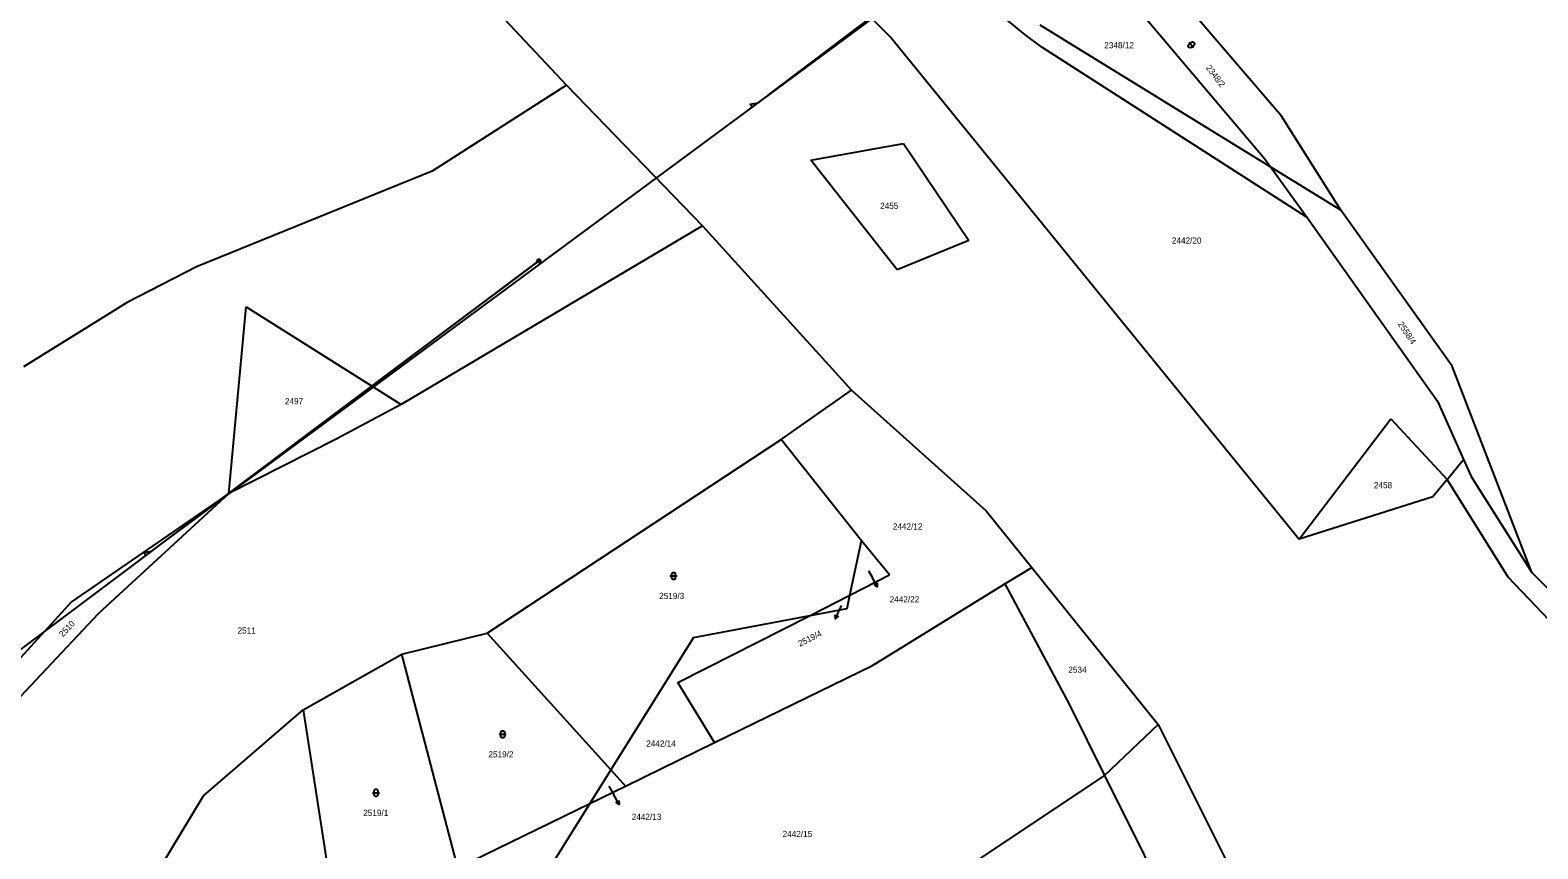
# Model space of a CAD drawing. Extents: x -747792 to -745414, y -1093712 to -1091463.
# Drawn here: x -747200 to -746990.9, y -1092715.2 to -1092601.7 of the extents above; entities that cross this region are included whole.
import ezdxf

# ---------------------------------------------------------------- set-up
doc = ezdxf.new("R2010")
doc.units = 0
for name, color, linetype in [('Pracovní_bod JDTM STC_VC', 7, 'Continuous'), ('Pracovní_bod JDTM STC_VC - číslo', 7, 'Continuous'), ('Pracovní_bod NN - výška', 7, 'Continuous'), ('Pracovní_bod polohopisu - výška', 7, 'Continuous'), ('Pracovní_bod polohopisu - číslo', 7, 'Continuous')]:
    doc.layers.add(name, color=color, linetype=linetype)

msp = doc.modelspace()

# ---------------------------------------------------------------- linework, layer by layer
at = {"layer": 'Pracovní_bod JDTM STC_VC - číslo'}
for points in [[(-747038.97, -1092603.39), (-747038.82, -1092603.33), (-747038.67, -1092603.37), (-747038.57, -1092603.49), (-747038.56, -1092603.64), (-747038.64, -1092603.77), (-747039.02, -1092604.09), (-747039.17, -1092604.15), (-747039.32, -1092604.11), (-747039.42, -1092603.99), (-747039.43, -1092603.84), (-747039.35, -1092603.71)], [(-747111.06, -1092677.12), (-747111.01, -1092676.98), (-747110.89, -1092676.89), (-747110.73, -1092676.89), (-747110.6, -1092676.98), (-747110.56, -1092677.12), (-747110.56, -1092677.62), (-747110.6, -1092677.77), (-747110.73, -1092677.85), (-747110.89, -1092677.85), (-747111.01, -1092677.77), (-747111.06, -1092677.62)], [(-747134.75, -1092699.08), (-747134.7, -1092698.94), (-747134.58, -1092698.85), (-747134.42, -1092698.85), (-747134.29, -1092698.94), (-747134.24, -1092699.08), (-747134.24, -1092699.58), (-747134.29, -1092699.73), (-747134.42, -1092699.81), (-747134.58, -1092699.81), (-747134.7, -1092699.73), (-747134.75, -1092699.58)], [(-747152.32, -1092707.2), (-747152.27, -1092707.05), (-747152.15, -1092706.96), (-747151.99, -1092706.96), (-747151.86, -1092707.05), (-747151.82, -1092707.2), (-747151.82, -1092707.7), (-747151.86, -1092707.84), (-747151.99, -1092707.94), (-747152.15, -1092707.94), (-747152.27, -1092707.84), (-747152.32, -1092707.7)]]:
    msp.add_lwpolyline(points, close=True, dxfattribs=at)
for points in [[(-747039.32, -1092603.36), (-747038.91, -1092603.84), (-747038.68, -1092604.12)], [(-747111.31, -1092677.37), (-747110.68, -1092677.37), (-747110.31, -1092677.37)], [(-747135, -1092699.33), (-747134.36, -1092699.33), (-747134, -1092699.33)], [(-747152.57, -1092707.45), (-747151.93, -1092707.45), (-747151.57, -1092707.45)]]:
    msp.add_lwpolyline(points, dxfattribs=at)
at = {"layer": 'Pracovní_bod NN - výška'}
for points in [[(-747062.09, -1092602.28), (-747127.32, -1092548.77)], [(-747108.12, -1092575.08), (-747080.59, -1092602.79)], [(-747152.98, -1092580.18), (-747125.63, -1092609.32)], [(-747026.5, -1092613.63), (-747044.33, -1092592.76)], [(-747049.25, -1092595.36), (-747028.84, -1092619.47)], [(-747027.96, -1092620.69), (-747059.94, -1092601.01)], [(-747080.59, -1092602.79), (-747024.03, -1092672.29)], [(-747059.73, -1092604.05), (-747062.09, -1092602.28)], [(-747022.93, -1092627.66), (-747059.73, -1092604.05)], [(-747125.63, -1092609.32), (-747144.3, -1092621.26)], [(-747125.63, -1092609.32), (-747106.81, -1092628.82)], [(-747018.24, -1092626.67), (-747026.5, -1092613.63)], [(-747091.74, -1092619.7), (-747078.9, -1092617.43)], [(-747078.9, -1092617.43), (-747069.83, -1092630.85)], [(-747079.77, -1092634.91), (-747091.74, -1092619.7)], [(-747028.84, -1092619.47), (-747027.96, -1092620.69)], [(-747027.96, -1092620.69), (-747022.93, -1092627.66)], [(-747018.24, -1092626.67), (-747027.96, -1092620.69)], [(-747144.3, -1092621.26), (-747176.95, -1092634.52)], [(-747002.81, -1092648.3), (-747018.24, -1092626.67)], [(-747106.81, -1092628.82), (-747148.57, -1092653.6)], [(-747106.81, -1092628.82), (-747086.14, -1092651.63)], [(-747022.93, -1092627.66), (-747004.86, -1092653.12)], [(-747069.83, -1092630.85), (-747079.77, -1092634.91)], [(-747176.95, -1092634.52), (-747186.6, -1092639.44)], [(-747186.6, -1092639.44), (-747200.94, -1092648.37)], [(-747172.48, -1092665.96), (-747170.07, -1092640.05)], [(-747170.07, -1092640.05), (-747148.57, -1092653.6)], [(-746991.75, -1092676.92), (-747002.81, -1092648.3)], [(-747095.89, -1092658.47), (-747086.14, -1092651.63)], [(-747086.14, -1092651.63), (-747067.45, -1092668.35)], [(-747148.57, -1092653.6), (-747157.6, -1092658.4)], [(-747004.86, -1092653.12), (-747001.24, -1092661.22)], [(-747024.03, -1092672.29), (-747011.32, -1092655.6)], [(-747011.32, -1092655.6), (-747003.51, -1092664)], [(-747157.6, -1092658.4), (-747172.48, -1092665.96)], [(-747136.66, -1092685.33), (-747095.89, -1092658.47)], [(-747084.75, -1092672.49), (-747095.89, -1092658.47)], [(-747003.51, -1092664), (-747001.24, -1092661.22)], [(-747001.24, -1092661.22), (-747000.19, -1092663.57)], [(-747003.51, -1092664), (-747005.48, -1092666.41)], [(-746995.03, -1092677.54), (-747003.51, -1092664)], [(-747000.19, -1092663.57), (-746991.75, -1092676.92)], [(-747172.48, -1092665.96), (-747194.29, -1092680.96)], [(-747190.58, -1092682.6), (-747172.48, -1092665.96)], [(-747005.48, -1092666.41), (-747024.03, -1092672.29)], [(-747067.45, -1092668.35), (-747061.13, -1092676.19)], [(-747086.36, -1092680.05), (-747084.75, -1092672.49)], [(-747080.85, -1092677.23), (-747084.75, -1092672.49)], [(-747086.36, -1092680.05), (-747080.85, -1092677.23)], [(-747064.85, -1092678.48), (-747061.13, -1092676.19)], [(-747061.13, -1092676.19), (-747043.57, -1092697.97)], [(-746991.75, -1092676.92), (-746972.43, -1092696.23)], [(-747083.19, -1092689.78), (-747064.85, -1092678.48)], [(-747064.85, -1092678.48), (-747055.89, -1092695.25)], [(-746975.16, -1092698.37), (-746995.03, -1092677.54)], [(-747194.29, -1092680.96), (-747207.98, -1092695.95)], [(-747091.84, -1092682.84), (-747086.36, -1092680.05)], [(-747086.74, -1092681.87), (-747086.36, -1092680.05)], [(-747206.43, -1092699.4), (-747190.58, -1092682.6)], [(-747110.19, -1092692.17), (-747091.84, -1092682.84)], [(-747108.03, -1092685.91), (-747091.84, -1092682.84)], [(-747091.84, -1092682.84), (-747086.74, -1092681.87)], [(-747148.51, -1092688.2), (-747136.66, -1092685.33)], [(-747136.66, -1092685.33), (-747119.51, -1092704.28)], [(-747108.03, -1092685.91), (-747119.51, -1092704.28)], [(-747162.16, -1092695.95), (-747148.51, -1092688.2)], [(-747140.7, -1092717.84), (-747148.51, -1092688.2)], [(-747105.14, -1092700.48), (-747083.19, -1092689.78)], [(-747105.14, -1092700.48), (-747110.19, -1092692.17)], [(-747175.98, -1092707.86), (-747162.16, -1092695.95)], [(-747162.16, -1092695.95), (-747158.02, -1092722.81)], [(-747055.89, -1092695.25), (-747051.05, -1092705.03)], [(-747043.57, -1092697.97), (-747051.05, -1092705.03)], [(-747043.57, -1092697.97), (-747019.81, -1092745.51)], [(-747117.49, -1092706.51), (-747105.14, -1092700.48)], [(-747119.51, -1092704.28), (-747122.4, -1092708.91)], [(-747119.51, -1092704.28), (-747117.49, -1092706.51)], [(-747122.4, -1092708.91), (-747117.49, -1092706.51)], [(-747051.05, -1092705.03), (-747075.8, -1092721.53)], [(-747051.05, -1092705.03), (-747040.06, -1092727.04)], [(-747192.67, -1092735.5), (-747175.98, -1092707.86)], [(-747140.7, -1092717.84), (-747122.4, -1092708.91)], [(-747122.4, -1092708.91), (-747134.18, -1092727.75)]]:
    msp.add_lwpolyline(points, dxfattribs=at)
at = {"layer": 'Pracovní_bod polohopisu - výška'}
for points in [[(-747083.75, -1092676.66), (-747083.26, -1092677.55)], [(-747082.54, -1092678.87), (-747083.26, -1092677.55)], [(-747082.56, -1092678.31), (-747082.54, -1092678.87), (-747083, -1092678.55)], [(-747087.54, -1092681.48), (-747087.74, -1092681.94)], [(-747087.91, -1092682.96), (-747088.34, -1092683.31), (-747088.37, -1092682.76)], [(-747088.34, -1092683.31), (-747087.74, -1092681.94)], [(-747119.78, -1092706.51), (-747119.08, -1092707.75)], [(-747118.34, -1092709.06), (-747119.08, -1092707.75)], [(-747118.37, -1092708.5), (-747118.34, -1092709.06), (-747118.8, -1092708.74)]]:
    msp.add_lwpolyline(points, dxfattribs=at)
at = {"layer": 'Pracovní_bod polohopisu - číslo'}
for points in [[(-747097.67, -1092610.73), (-746937.26, -1092489.46), (-747018.86, -1092551.15)], [(-747181.77, -1092672.87), (-747016.39, -1092550.67), (-747100.49, -1092612.81)], [(-747100.29, -1092612.66), (-747099.89, -1092612.36), (-747100.18, -1092611.96), (-747099.08, -1092611.77), (-747097.88, -1092610.88)], [(-747236.86, -1092714.14), (-747129.49, -1092633.7), (-747184.58, -1092674.97)], [(-747129.57, -1092633.46), (-747129.41, -1092633.46), (-747129.28, -1092633.55), (-747129.23, -1092633.69), (-747129.28, -1092633.84), (-747129.41, -1092633.93), (-747129.57, -1092633.93), (-747129.69, -1092633.84), (-747129.74, -1092633.69), (-747129.69, -1092633.55), (-747129.57, -1092633.46), (-747129.55, -1092633.48), (-747129.43, -1092633.48), (-747129.35, -1092633.52), (-747129.63, -1092633.52), (-747129.67, -1092633.56), (-747129.31, -1092633.56), (-747129.31, -1092633.6), (-747129.67, -1092633.6), (-747129.69, -1092633.64), (-747129.29, -1092633.64), (-747129.27, -1092633.68), (-747129.71, -1092633.68), (-747129.71, -1092633.72), (-747129.27, -1092633.72), (-747129.28, -1092633.76), (-747129.69, -1092633.76), (-747129.69, -1092633.8), (-747129.28, -1092633.8), (-747129.3, -1092633.84), (-747129.67, -1092633.84), (-747129.62, -1092633.88), (-747129.34, -1092633.88), (-747129.4, -1092633.92), (-747129.57, -1092633.92)], [(-747184.38, -1092674.82), (-747183.98, -1092674.52), (-747184.28, -1092674.12), (-747183.18, -1092673.92), (-747181.97, -1092673.02)]]:
    msp.add_lwpolyline(points, dxfattribs=at)

# ---------------------------------------------------------------- texts
at = {"layer": 'Pracovní_bod JDTM STC_VC'}
for s, height, p in [('2348/12', 0.85, (-747051.06, -1092604.2)), ('2455', 0.85, (-747082.15, -1092626.48)), ('2442/20', 0.85, (-747041.69, -1092631.29)), ('2497', 0.85, (-747164.7, -1092653.56)), ('2458', 0.85, (-747013.67, -1092665.21)), ('2442/12', 0.85, (-747080.39, -1092670.94)), ('2442/22', 0.05, (-747083.9, -1092676.66)), ('2519/3', 0.85, (-747112.8, -1092680.57)), ('2519/4', 0.05, (-747087.65, -1092681.48)), ('2511', 0.85, (-747171.27, -1092685.36)), ('2534', 0.85, (-747056.05, -1092690.8)), ('2442/14', 0.85, (-747114.6, -1092701.04)), ('2519/2', 0.85, (-747136.48, -1092702.53)), ('2442/13', 0.05, (-747119.92, -1092706.51)), ('2519/1', 0.85, (-747153.84, -1092710.65)), ('2442/15', 0.85, (-747095.68, -1092713.58))]:
    msp.add_text(s, height=height, dxfattribs=at).set_placement(p)
for s, rotation, p in [('2348/2', 307.22, (-747037.01, -1092606.93)), ('2558/4', 303.8968, (-747010.39, -1092642.46)), ('2510', 46.7534, (-747195.5, -1092685.9))]:
    msp.add_text(s, height=0.85, rotation=rotation, dxfattribs=at).set_placement(p)
at = {"layer": 'Pracovní_bod polohopisu - výška'}
for s, p in [('2442/22', (-747080.83, -1092681.04)), ('2442/13', (-747116.6, -1092711.21))]:
    msp.add_text(s, height=0.85, dxfattribs=at).set_placement(p)
msp.add_text('2519/4', height=0.85, rotation=26.5852, dxfattribs=at).set_placement((-747093.26, -1092687.2))

doc.saveas('drawing.dxf')
